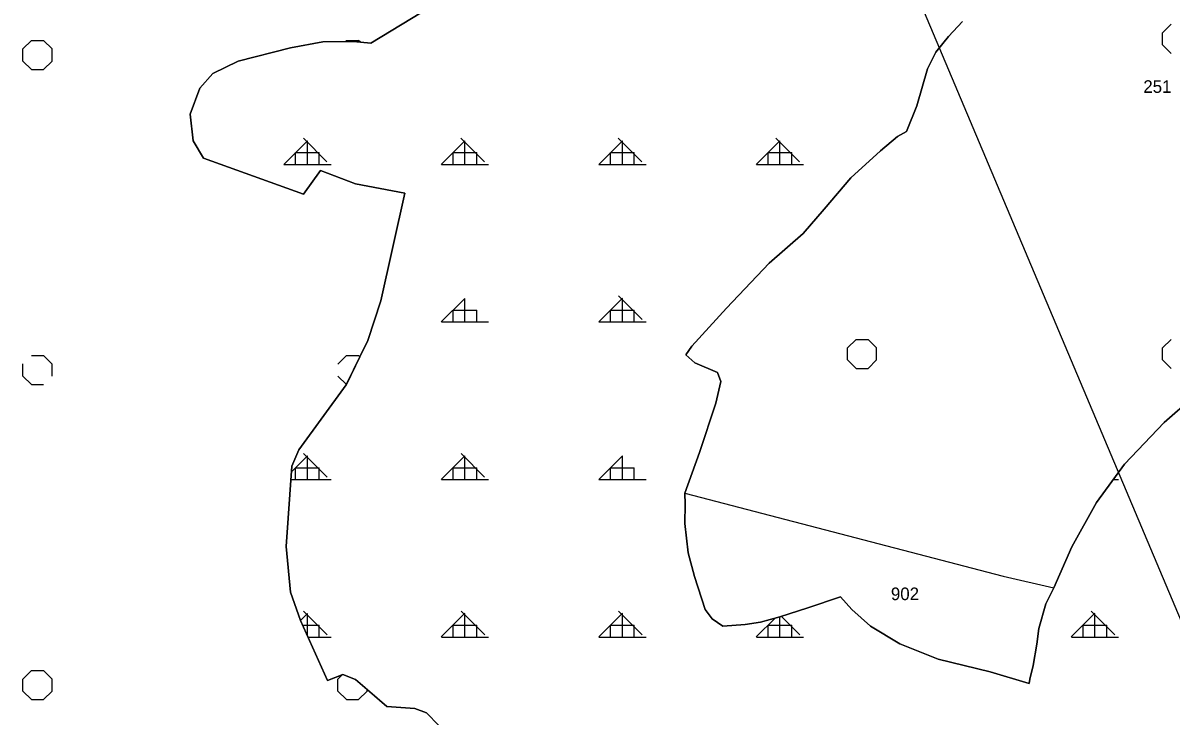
# Model space of a CAD drawing. Extents: x 410727 to 412947, y 4463506 to 4466382.
# Drawn here: x 411332 to 411696.5, y 4465172.3 to 4465392.3 of the extents above; entities that cross this region are included whole.
import ezdxf

# ---------------------------------------------------------------- set-up
doc = ezdxf.new("R2010")
doc.units = 0
for name, color, linetype in [('ADAKENARI', 7, 'Continuous'), ('KDS_PARSEL_NO', 7, 'Continuous'), ('KDS_PL', 7, 'Continuous'), ('LJ_ÇERÇEVE', 7, 'Continuous'), ('PL_AYA_ORMAN', 7, 'Continuous'), ('PL_KA_TARIM_DIGER', 7, 'Continuous'), ('TR_ORMAN', 7, 'Continuous'), ('TR_TARIMALANI', 7, 'Continuous')]:
    doc.layers.add(name, color=color, linetype=linetype)

msp = doc.modelspace()

# ---------------------------------------------------------------- linework, layer by layer
at = {"layer": 'ADAKENARI'}
for p, q in [((411442.41, 4465385.9), (411471.18, 4465403.51)), ((411630.3, 4465392.76), (411625.8, 4465388.07)), ((411416.96, 4465384.44), (411427.14, 4465386.32)), ((411427.14, 4465386.32), (411436.9, 4465386.42)), ((411436.9, 4465386.42), (411442.41, 4465385.9)), ((411436.9, 4465386.42), (411442.41, 4465385.9)), ((411625.8, 4465388.07), (411621.83, 4465383.02)), ((411400.33, 4465380.17), (411416.96, 4465384.44)), ((411621.83, 4465383.02), (411619.13, 4465377.78)), ((411392.23, 4465376.31), (411400.33, 4465380.17)), ((411619.13, 4465377.78), (411615.71, 4465366.05)), ((411388.18, 4465371.62), (411392.23, 4465376.31)), ((411385.06, 4465363.39), (411388.18, 4465371.62)), ((411386, 4465354.95), (411385.06, 4465363.39)), ((411615.71, 4465366.05), (411612.47, 4465357.93)), ((411609.59, 4465356.31), (411604.18, 4465351.79)), ((411612.47, 4465357.93), (411609.59, 4465356.31)), ((411389.32, 4465349.43), (411386, 4465354.95)), ((411421.01, 4465337.97), (411389.32, 4465349.43)), ((411604.18, 4465351.79), (411594.82, 4465343.13)), ((411426.41, 4465345.47), (411421.01, 4465337.97)), ((411437.53, 4465341.3), (411426.41, 4465345.47)), ((411453.21, 4465338.28), (411437.53, 4465341.3)), ((411594.82, 4465343.13), (411586.35, 4465333.21)), ((411445.63, 4465304.1), (411453.21, 4465338.28)), ((411586.35, 4465333.21), (411579.69, 4465325.45)), ((411579.69, 4465325.45), (411568.88, 4465316.06)), ((411568.88, 4465316.06), (411555.37, 4465301.8)), ((411441.47, 4465291.49), (411445.63, 4465304.1)), ((411555.37, 4465301.8), (411544.38, 4465289.71)), ((411434.62, 4465277.42), (411441.47, 4465291.49)), ((411544.38, 4465289.71), (411542.4, 4465287)), ((411542.4, 4465287), (411545.28, 4465284.48)), ((411545.28, 4465284.48), (411552.49, 4465281.41)), ((411552.49, 4465281.41), (411553.57, 4465278.52)), ((411419.55, 4465256.79), (411434.62, 4465277.42)), ((411553.57, 4465278.52), (411551.95, 4465271.67)), ((411694.29, 4465265.48), (411703.49, 4465273.54)), ((411551.95, 4465271.67), (411546.73, 4465255.96)), ((411681.65, 4465252.23), (411694.29, 4465265.48)), ((411417.37, 4465251.68), (411419.55, 4465256.79)), ((411546.73, 4465255.96), (411542.16, 4465243.04)), ((411415.6, 4465226.15), (411417.37, 4465251.68)), ((411672.74, 4465240.14), (411681.65, 4465252.23)), ((411542.16, 4465243.04), (411542.25, 4465239.55)), ((411542.25, 4465239.55), (411542.08, 4465233.43)), ((411664.98, 4465226.04), (411672.74, 4465240.14)), ((411542.08, 4465233.43), (411543.13, 4465224.15)), ((411416.96, 4465211.67), (411415.6, 4465226.15)), ((411659.3, 4465213.08), (411664.98, 4465226.04)), ((411543.13, 4465224.15), (411545.22, 4465216.63)), ((411545.22, 4465216.63), (411548.54, 4465206.13)), ((411420.07, 4465202.71), (411416.96, 4465211.67)), ((411581.2, 4465206.66), (411591.5, 4465210.16)), ((411591.5, 4465210.16), (411595.17, 4465206.13)), ((411656.74, 4465207.95), (411659.3, 4465213.08)), ((411572.29, 4465203.86), (411581.2, 4465206.66)), ((411654.52, 4465200.17), (411656.74, 4465207.95)), ((411428.69, 4465183.64), (411420.07, 4465202.71)), ((411548.54, 4465206.13), (411550.81, 4465203.16)), ((411550.81, 4465203.16), (411554.13, 4465200.88)), ((411566.18, 4465202.11), (411572.29, 4465203.86)), ((411595.17, 4465206.13), (411601.1, 4465200.88)), ((411554.13, 4465200.88), (411561.29, 4465201.41)), ((411561.29, 4465201.41), (411566.18, 4465202.11)), ((411601.1, 4465200.88), (411610.36, 4465195.28)), ((411653.82, 4465195.16), (411654.52, 4465200.17)), ((411610.36, 4465195.28), (411622.58, 4465190.38)), ((411652.71, 4465188.35), (411653.82, 4465195.16)), ((411622.58, 4465190.38), (411639, 4465186.36)), ((411651.6, 4465184.04), (411652.71, 4465188.35)), ((411433.58, 4465185.51), (411428.69, 4465183.64)), ((411437.53, 4465183.95), (411433.58, 4465185.51)), ((411639, 4465186.36), (411651.46, 4465182.65)), ((411447.5, 4465175.41), (411437.53, 4465183.95)), ((411651.46, 4465182.65), (411651.6, 4465184.04)), ((411456.43, 4465174.68), (411447.5, 4465175.41)), ((411460.07, 4465173.32), (411456.43, 4465174.68)), ((411464.02, 4465169.36), (411460.07, 4465173.32))]:
    msp.add_line(p, q, dxfattribs=at)
at = {"layer": 'KDS_PL'}
for p, q in [((411442.41, 4465385.9), (411471.18, 4465403.51)), ((411625.8, 4465388.07), (411630.3, 4465392.76)), ((411416.96, 4465384.44), (411427.14, 4465386.32)), ((411427.14, 4465386.32), (411436.9, 4465386.42)), ((411436.9, 4465386.42), (411442.41, 4465385.9)), ((411621.83, 4465383.02), (411625.8, 4465388.07)), ((411400.33, 4465380.17), (411416.96, 4465384.44)), ((411619.13, 4465377.78), (411621.83, 4465383.02)), ((411392.23, 4465376.31), (411400.33, 4465380.17)), ((411615.71, 4465366.05), (411619.13, 4465377.78)), ((411388.18, 4465371.62), (411392.23, 4465376.31)), ((411385.06, 4465363.39), (411388.18, 4465371.62)), ((411386, 4465354.95), (411385.06, 4465363.39)), ((411612.47, 4465357.93), (411615.71, 4465366.05)), ((411604.18, 4465351.79), (411609.59, 4465356.31)), ((411609.59, 4465356.31), (411612.47, 4465357.93)), ((411389.32, 4465349.43), (411386, 4465354.95)), ((411421.01, 4465337.97), (411389.32, 4465349.43)), ((411594.82, 4465343.13), (411604.18, 4465351.79)), ((411426.41, 4465345.47), (411421.01, 4465337.97)), ((411437.53, 4465341.3), (411426.41, 4465345.47)), ((411453.21, 4465338.28), (411437.53, 4465341.3)), ((411586.35, 4465333.21), (411594.82, 4465343.13)), ((411445.63, 4465304.1), (411453.21, 4465338.28)), ((411579.69, 4465325.45), (411586.35, 4465333.21)), ((411568.88, 4465316.06), (411579.69, 4465325.45)), ((411555.37, 4465301.8), (411568.88, 4465316.06)), ((411441.47, 4465291.49), (411445.63, 4465304.1)), ((411544.38, 4465289.71), (411555.37, 4465301.8)), ((411434.62, 4465277.42), (411441.47, 4465291.49)), ((411542.4, 4465287), (411544.38, 4465289.71)), ((411545.28, 4465284.48), (411542.4, 4465287)), ((411552.49, 4465281.41), (411545.28, 4465284.48)), ((411553.57, 4465278.52), (411552.49, 4465281.41)), ((411419.55, 4465256.79), (411434.62, 4465277.42)), ((411551.95, 4465271.67), (411553.57, 4465278.52)), ((411694.29, 4465265.48), (411703.49, 4465273.54)), ((411546.73, 4465255.96), (411551.95, 4465271.67)), ((411681.65, 4465252.23), (411694.29, 4465265.48)), ((411417.37, 4465251.68), (411419.55, 4465256.79)), ((411542.16, 4465243.04), (411546.73, 4465255.96)), ((411415.6, 4465226.15), (411417.37, 4465251.68)), ((411672.74, 4465240.14), (411681.65, 4465252.23)), ((411542.16, 4465243.04), (411643.13, 4465216.75)), ((411542.25, 4465239.55), (411542.16, 4465243.04)), ((411542.08, 4465233.43), (411542.25, 4465239.55)), ((411664.98, 4465226.04), (411672.74, 4465240.14)), ((411543.13, 4465224.15), (411542.08, 4465233.43)), ((411416.96, 4465211.67), (411415.6, 4465226.15)), ((411659.3, 4465213.08), (411664.98, 4465226.04)), ((411545.22, 4465216.63), (411543.13, 4465224.15)), ((411548.54, 4465206.13), (411545.22, 4465216.63)), ((411643.13, 4465216.75), (411659.3, 4465213.08)), ((411420.07, 4465202.71), (411416.96, 4465211.67)), ((411591.5, 4465210.16), (411581.2, 4465206.66)), ((411595.17, 4465206.13), (411591.5, 4465210.16)), ((411659.3, 4465213.08), (411656.74, 4465207.95)), ((411581.2, 4465206.66), (411572.29, 4465203.86)), ((411656.74, 4465207.95), (411654.52, 4465200.17)), ((411428.69, 4465183.64), (411420.07, 4465202.71)), ((411550.81, 4465203.16), (411548.54, 4465206.13)), ((411554.13, 4465200.88), (411550.81, 4465203.16)), ((411572.29, 4465203.86), (411566.18, 4465202.11)), ((411601.1, 4465200.88), (411595.17, 4465206.13)), ((411561.29, 4465201.41), (411554.13, 4465200.88)), ((411566.18, 4465202.11), (411561.29, 4465201.41)), ((411610.36, 4465195.28), (411601.1, 4465200.88)), ((411654.52, 4465200.17), (411653.82, 4465195.16)), ((411622.58, 4465190.38), (411610.36, 4465195.28)), ((411653.82, 4465195.16), (411652.71, 4465188.35)), ((411639, 4465186.36), (411622.58, 4465190.38)), ((411652.71, 4465188.35), (411651.6, 4465184.04)), ((411433.58, 4465185.51), (411428.69, 4465183.64)), ((411437.53, 4465183.95), (411433.58, 4465185.51)), ((411651.46, 4465182.65), (411639, 4465186.36)), ((411447.5, 4465175.41), (411437.53, 4465183.95)), ((411651.6, 4465184.04), (411651.46, 4465182.65)), ((411456.43, 4465174.68), (411447.5, 4465175.41)), ((411460.07, 4465173.32), (411456.43, 4465174.68)), ((411464.02, 4465169.36), (411460.07, 4465173.32))]:
    msp.add_line(p, q, dxfattribs=at)
at = {"layer": 'LJ_ÇERÇEVE'}
msp.add_line((412177.76, 4464068.35), (411528.62, 4465608.26), dxfattribs=at)
at = {"layer": 'PL_AYA_ORMAN'}
for points in [[(411471.18, 4465403.51), (411442.41, 4465385.9), (411439.11, 4465386.21), (411436.9, 4465386.42), (411434.31, 4465386.39), (411427.14, 4465386.32), (411416.96, 4465384.44), (411400.33, 4465380.17), (411392.23, 4465376.31), (411388.18, 4465371.62), (411385.06, 4465363.39), (411386, 4465354.95), (411389.32, 4465349.43), (411421.01, 4465337.97), (411426.41, 4465345.47), (411437.53, 4465341.3), (411453.21, 4465338.28), (411445.63, 4465304.1), (411441.47, 4465291.49), (411438.97, 4465286.35), (411434.68, 4465277.56), (411434.62, 4465277.42), (411419.55, 4465256.79), (411417.37, 4465251.68), (411415.6, 4465226.15), (411416.96, 4465211.67), (411420.07, 4465202.71), (411428.69, 4465183.64), (411433.34, 4465185.42), (411433.58, 4465185.51), (411437.53, 4465183.95), (411441.25, 4465180.76), (411447.5, 4465175.41), (411456.43, 4465174.68), (411460.07, 4465173.32), (411464.02, 4465169.36)], [(411703.49, 4465273.54), (411694.29, 4465265.48), (411681.65, 4465252.23), (411672.74, 4465240.14), (411664.98, 4465226.04), (411659.3, 4465213.08), (411656.74, 4465207.95), (411654.52, 4465200.17), (411653.82, 4465195.16), (411652.71, 4465188.35), (411651.6, 4465184.04), (411651.46, 4465182.65), (411639, 4465186.36), (411622.58, 4465190.38), (411610.36, 4465195.28), (411601.1, 4465200.88), (411595.17, 4465206.13), (411591.5, 4465210.16), (411581.2, 4465206.66), (411572.29, 4465203.86), (411566.18, 4465202.11), (411561.29, 4465201.41), (411554.13, 4465200.88), (411550.81, 4465203.16), (411548.54, 4465206.13), (411545.22, 4465216.63), (411543.13, 4465224.15), (411542.08, 4465233.43), (411542.25, 4465239.55), (411542.16, 4465243.04), (411546.73, 4465255.96), (411551.95, 4465271.67), (411553.57, 4465278.52), (411552.49, 4465281.41), (411545.28, 4465284.48), (411542.4, 4465287), (411544.38, 4465289.71), (411555.37, 4465301.8), (411568.88, 4465316.06), (411579.69, 4465325.45), (411586.35, 4465333.21), (411594.82, 4465343.13), (411604.18, 4465351.79), (411609.59, 4465356.31), (411612.47, 4465357.93), (411615.71, 4465366.05), (411619.13, 4465377.78), (411621.83, 4465383.02), (411625.8, 4465388.07), (411630.3, 4465392.76)]]:
    msp.add_lwpolyline(points, dxfattribs=at)
at = {"layer": 'PL_KA_TARIM_DIGER'}
for points in [[(411464.02, 4465169.36), (411460.07, 4465173.32), (411456.43, 4465174.68), (411447.5, 4465175.41), (411437.53, 4465183.95), (411433.58, 4465185.51), (411428.69, 4465183.64), (411420.07, 4465202.71), (411416.96, 4465211.67), (411415.6, 4465226.15), (411417.37, 4465251.68), (411419.55, 4465256.79), (411434.62, 4465277.42), (411441.47, 4465291.49), (411445.63, 4465304.1), (411453.21, 4465338.28), (411437.53, 4465341.3), (411426.41, 4465345.47), (411421.01, 4465337.97), (411389.32, 4465349.43), (411386, 4465354.95), (411385.06, 4465363.39), (411388.18, 4465371.62), (411392.23, 4465376.31), (411400.33, 4465380.17), (411416.96, 4465384.44), (411427.14, 4465386.32), (411436.9, 4465386.42), (411442.41, 4465385.9), (411471.18, 4465403.51)], [(411630.3, 4465392.76), (411625.8, 4465388.07), (411621.83, 4465383.02), (411619.13, 4465377.78), (411615.71, 4465366.05), (411612.47, 4465357.93), (411609.59, 4465356.31), (411604.18, 4465351.79), (411594.82, 4465343.13), (411586.35, 4465333.21), (411579.69, 4465325.45), (411568.88, 4465316.06), (411555.37, 4465301.8), (411544.38, 4465289.71), (411542.4, 4465287), (411545.28, 4465284.48), (411552.49, 4465281.41), (411553.57, 4465278.52), (411551.95, 4465271.67), (411546.73, 4465255.96), (411542.16, 4465243.04), (411542.25, 4465239.55), (411542.08, 4465233.43), (411543.13, 4465224.15), (411545.22, 4465216.63), (411548.54, 4465206.13), (411550.81, 4465203.16), (411554.13, 4465200.88), (411561.29, 4465201.41), (411566.18, 4465202.11), (411572.29, 4465203.86), (411581.2, 4465206.66), (411591.5, 4465210.16), (411595.17, 4465206.13), (411601.1, 4465200.88), (411610.36, 4465195.28), (411622.58, 4465190.38), (411639, 4465186.36), (411651.46, 4465182.65), (411651.6, 4465184.04), (411652.71, 4465188.35), (411653.82, 4465195.16), (411654.52, 4465200.17), (411656.74, 4465207.95), (411659.3, 4465213.08), (411664.98, 4465226.04), (411672.74, 4465240.14), (411681.65, 4465252.23), (411694.29, 4465265.48), (411703.49, 4465273.54)]]:
    msp.add_lwpolyline(points, dxfattribs=at)
at = {"layer": 'TR_ORMAN'}
for p, q in [((411428.5, 4465348.21), (411421, 4465355.71)), ((411428.5, 4465348.21), (411421, 4465355.71)), ((411478.49, 4465348.21), (411470.99, 4465355.71)), ((411528.48, 4465348.21), (411520.99, 4465355.71)), ((411578.48, 4465348.21), (411570.98, 4465355.71)), ((411414.8, 4465347.41), (411422.3, 4465354.91)), ((411414.8, 4465347.41), (411422.3, 4465354.91)), ((411422.31, 4465347.41), (411422.31, 4465354.91)), ((411422.31, 4465347.41), (411422.31, 4465354.91)), ((411464.8, 4465347.41), (411472.3, 4465354.91)), ((411464.8, 4465347.41), (411472.3, 4465354.91)), ((411472.31, 4465347.41), (411472.31, 4465354.91)), ((411472.31, 4465347.41), (411472.31, 4465354.91)), ((411514.8, 4465347.42), (411522.29, 4465354.92)), ((411522.31, 4465347.41), (411522.31, 4465354.91)), ((411564.8, 4465347.43), (411572.29, 4465354.93)), ((411572.31, 4465347.41), (411572.31, 4465354.91)), ((411418.56, 4465347.41), (411418.56, 4465351.16)), ((411418.56, 4465347.41), (411418.56, 4465351.16)), ((411418.56, 4465351.16), (411426.06, 4465351.16)), ((411426.06, 4465347.41), (411426.06, 4465351.16)), ((411426.06, 4465347.41), (411426.06, 4465351.16)), ((411468.56, 4465347.41), (411468.56, 4465351.16)), ((411468.56, 4465347.41), (411468.56, 4465351.16)), ((411468.56, 4465351.16), (411476.06, 4465351.16)), ((411476.06, 4465347.41), (411476.06, 4465351.16)), ((411476.06, 4465347.41), (411476.06, 4465351.16)), ((411518.56, 4465347.41), (411518.56, 4465351.16)), ((411518.56, 4465351.16), (411526.06, 4465351.16)), ((411526.06, 4465347.41), (411526.06, 4465351.16)), ((411568.56, 4465347.41), (411568.56, 4465351.16)), ((411568.56, 4465351.16), (411576.06, 4465351.16)), ((411576.06, 4465347.41), (411576.06, 4465351.16)), ((411414.81, 4465347.41), (411429.81, 4465347.41)), ((411464.81, 4465347.41), (411479.81, 4465347.41)), ((411514.81, 4465347.41), (411529.81, 4465347.41)), ((411564.81, 4465347.41), (411579.81, 4465347.41)), ((411464.8, 4465297.42), (411472.3, 4465304.92)), ((411472.31, 4465297.41), (411472.31, 4465304.91)), ((411472.31, 4465297.41), (411472.31, 4465304.91)), ((411514.8, 4465297.43), (411522.29, 4465304.93)), ((411528.52, 4465298.18), (411521.02, 4465305.68)), ((411522.31, 4465297.41), (411522.31, 4465304.91)), ((411468.56, 4465297.41), (411468.56, 4465301.16)), ((411468.56, 4465297.41), (411468.56, 4465301.16)), ((411468.56, 4465301.16), (411476.06, 4465301.16)), ((411476.06, 4465297.41), (411476.06, 4465301.16)), ((411476.06, 4465297.41), (411476.06, 4465301.16)), ((411518.56, 4465297.41), (411518.56, 4465301.16)), ((411518.56, 4465301.16), (411526.06, 4465301.16)), ((411526.06, 4465297.41), (411526.06, 4465301.16)), ((411464.81, 4465297.41), (411479.81, 4465297.41)), ((411514.81, 4465297.41), (411529.81, 4465297.41)), ((411417.25, 4465249.87), (411422.3, 4465254.92)), ((411428.56, 4465248.16), (411421.06, 4465255.66)), ((411422.31, 4465247.41), (411422.31, 4465254.91)), ((411464.8, 4465247.43), (411472.3, 4465254.93)), ((411478.56, 4465248.16), (411471.06, 4465255.66)), ((411472.31, 4465247.41), (411472.31, 4465254.91)), ((411472.31, 4465247.41), (411472.31, 4465254.91)), ((411514.8, 4465247.44), (411522.29, 4465254.93)), ((411522.31, 4465247.41), (411522.31, 4465254.91)), ((411418.56, 4465251.16), (411426.06, 4465251.16)), ((411418.56, 4465247.41), (411418.56, 4465251.16)), ((411426.06, 4465247.41), (411426.06, 4465251.16)), ((411468.56, 4465251.16), (411476.06, 4465251.16)), ((411468.56, 4465247.41), (411468.56, 4465251.16)), ((411468.56, 4465247.41), (411468.56, 4465251.16)), ((411476.06, 4465247.41), (411476.06, 4465251.16)), ((411476.06, 4465247.41), (411476.06, 4465251.16)), ((411518.56, 4465251.16), (411526.06, 4465251.16)), ((411518.56, 4465247.41), (411518.56, 4465251.16)), ((411526.06, 4465247.41), (411526.06, 4465251.16)), ((411417.08, 4465247.41), (411429.81, 4465247.41)), ((411464.81, 4465247.41), (411479.81, 4465247.41)), ((411514.81, 4465247.41), (411529.81, 4465247.41)), ((411678.1, 4465247.41), (411679.81, 4465247.41)), ((411678.1, 4465247.41), (411679.81, 4465247.41)), ((411420.07, 4465202.71), (411422.3, 4465204.93)), ((411428.59, 4465198.14), (411421.1, 4465205.64)), ((411422.31, 4465197.75), (411422.31, 4465204.91)), ((411464.8, 4465197.44), (411472.3, 4465204.94)), ((411478.59, 4465198.14), (411471.09, 4465205.64)), ((411472.31, 4465197.41), (411472.31, 4465204.91)), ((411472.31, 4465197.41), (411472.31, 4465204.91)), ((411514.8, 4465197.44), (411522.29, 4465204.94)), ((411528.58, 4465198.14), (411521.08, 4465205.64)), ((411522.31, 4465197.41), (411522.31, 4465204.91)), ((411564.8, 4465197.45), (411570.77, 4465203.42)), ((411572.31, 4465197.41), (411572.31, 4465203.86)), ((411578.57, 4465198.14), (411572.72, 4465203.99)), ((411664.79, 4465197.46), (411672.29, 4465204.96)), ((411678.56, 4465198.14), (411671.06, 4465205.64)), ((411672.31, 4465197.41), (411672.31, 4465204.91)), ((411420.77, 4465201.16), (411426.06, 4465201.16)), ((411426.06, 4465197.41), (411426.06, 4465201.16)), ((411468.56, 4465197.41), (411468.56, 4465201.16)), ((411468.56, 4465197.41), (411468.56, 4465201.16)), ((411468.56, 4465201.16), (411476.06, 4465201.16)), ((411476.06, 4465197.41), (411476.06, 4465201.16)), ((411476.06, 4465197.41), (411476.06, 4465201.16)), ((411518.56, 4465197.41), (411518.56, 4465201.16)), ((411518.56, 4465201.16), (411526.06, 4465201.16)), ((411526.06, 4465197.41), (411526.06, 4465201.16)), ((411568.56, 4465197.41), (411568.56, 4465201.16)), ((411568.56, 4465201.16), (411576.06, 4465201.16)), ((411576.06, 4465197.41), (411576.06, 4465201.16)), ((411668.56, 4465197.41), (411668.56, 4465201.16)), ((411668.56, 4465201.16), (411676.06, 4465201.16)), ((411668.56, 4465201.16), (411676.06, 4465201.16)), ((411676.06, 4465197.41), (411676.06, 4465201.16)), ((411422.47, 4465197.41), (411429.81, 4465197.41)), ((411464.81, 4465197.41), (411479.81, 4465197.41)), ((411514.81, 4465197.41), (411529.81, 4465197.41)), ((411564.81, 4465197.41), (411579.81, 4465197.41)), ((411664.81, 4465197.41), (411679.81, 4465197.41)), ((411664.81, 4465197.41), (411679.81, 4465197.41))]:
    msp.add_line(p, q, dxfattribs=at)
at = {"layer": 'TR_TARIMALANI'}
for p, q in [((411693.74, 4465389.19), (411696.45, 4465391.9)), ((411693.74, 4465389.19), (411696.45, 4465391.9)), ((411693.75, 4465385.36), (411693.75, 4465389.19)), ((411693.75, 4465385.36), (411693.75, 4465389.19)), ((411332, 4465384.07), (411334.7, 4465386.78)), ((411332, 4465384.07), (411334.7, 4465386.78)), ((411334.71, 4465386.79), (411338.54, 4465386.79)), ((411334.71, 4465386.79), (411338.54, 4465386.79)), ((411341.25, 4465384.07), (411338.54, 4465386.78)), ((411341.25, 4465384.07), (411338.54, 4465386.78)), ((411434.31, 4465386.39), (411434.7, 4465386.78)), ((411434.31, 4465386.39), (411434.7, 4465386.78)), ((411434.71, 4465386.79), (411438.54, 4465386.79)), ((411439.11, 4465386.21), (411438.54, 4465386.78)), ((411696.45, 4465382.65), (411693.74, 4465385.36)), ((411696.45, 4465382.65), (411693.74, 4465385.36)), ((411332, 4465380.25), (411332, 4465384.08)), ((411332, 4465380.25), (411332, 4465384.08)), ((411341.25, 4465380.25), (411341.25, 4465384.08)), ((411341.25, 4465380.25), (411341.25, 4465384.08)), ((411334.71, 4465377.53), (411332, 4465380.24)), ((411334.71, 4465377.53), (411332, 4465380.24)), ((411334.71, 4465377.54), (411338.54, 4465377.54)), ((411334.71, 4465377.54), (411338.54, 4465377.54)), ((411338.54, 4465377.53), (411341.24, 4465380.24)), ((411338.54, 4465377.53), (411341.24, 4465380.24)), ((411593.74, 4465289.19), (411596.45, 4465291.9)), ((411593.74, 4465289.19), (411596.45, 4465291.9)), ((411596.46, 4465291.9), (411600.29, 4465291.9)), ((411596.46, 4465291.9), (411600.29, 4465291.9)), ((411602.99, 4465289.19), (411600.28, 4465291.9)), ((411602.99, 4465289.19), (411600.28, 4465291.9)), ((411693.74, 4465289.19), (411696.45, 4465291.9)), ((411693.74, 4465289.19), (411696.45, 4465291.9)), ((411334.71, 4465286.79), (411338.54, 4465286.79)), ((411334.71, 4465286.79), (411338.54, 4465286.79)), ((411334.71, 4465286.79), (411338.54, 4465286.79)), ((411334.71, 4465286.79), (411338.54, 4465286.79)), ((411341.25, 4465284.07), (411338.54, 4465286.78)), ((411341.25, 4465284.07), (411338.54, 4465286.78)), ((411431.99, 4465284.07), (411434.7, 4465286.78)), ((411434.71, 4465286.79), (411438.54, 4465286.79)), ((411434.71, 4465286.79), (411438.54, 4465286.79)), ((411438.97, 4465286.35), (411438.54, 4465286.78)), ((411593.75, 4465285.36), (411593.75, 4465289.19)), ((411593.75, 4465285.36), (411593.75, 4465289.19)), ((411603, 4465285.36), (411603, 4465289.19)), ((411603, 4465285.36), (411603, 4465289.19)), ((411693.75, 4465285.36), (411693.75, 4465289.19)), ((411693.75, 4465285.36), (411693.75, 4465289.19)), ((411332, 4465280.25), (411332, 4465284.08)), ((411332, 4465280.25), (411332, 4465284.08)), ((411341.25, 4465280.25), (411341.25, 4465284.08)), ((411341.25, 4465280.25), (411341.25, 4465284.08)), ((411596.45, 4465282.65), (411593.74, 4465285.36)), ((411596.45, 4465282.65), (411593.74, 4465285.36)), ((411600.28, 4465282.65), (411602.99, 4465285.36)), ((411600.28, 4465282.65), (411602.99, 4465285.36)), ((411696.45, 4465282.65), (411693.74, 4465285.36)), ((411696.45, 4465282.65), (411693.74, 4465285.36)), ((411334.71, 4465277.53), (411332, 4465280.24)), ((411334.71, 4465277.53), (411332, 4465280.24)), ((411434.68, 4465277.56), (411432, 4465280.24)), ((411596.46, 4465282.65), (411600.29, 4465282.65)), ((411596.46, 4465282.65), (411600.29, 4465282.65)), ((411334.71, 4465277.54), (411338.54, 4465277.54)), ((411334.71, 4465277.54), (411338.54, 4465277.54)), ((411334.71, 4465277.54), (411338.54, 4465277.54)), ((411334.71, 4465277.54), (411338.54, 4465277.54)), ((411332, 4465184.08), (411334.7, 4465186.78)), ((411332, 4465184.08), (411334.7, 4465186.78)), ((411334.71, 4465186.79), (411338.54, 4465186.79)), ((411334.71, 4465186.79), (411338.54, 4465186.79)), ((411341.25, 4465184.08), (411338.54, 4465186.78)), ((411341.25, 4465184.08), (411338.54, 4465186.78)), ((411431.99, 4465184.08), (411433.34, 4465185.42)), ((411332, 4465180.25), (411332, 4465184.08)), ((411332, 4465180.25), (411332, 4465184.08)), ((411341.25, 4465180.25), (411341.25, 4465184.08)), ((411341.25, 4465180.25), (411341.25, 4465184.08)), ((411432, 4465180.25), (411432, 4465184.08)), ((411441.25, 4465180.25), (411441.25, 4465180.76)), ((411334.71, 4465177.54), (411332, 4465180.24)), ((411334.71, 4465177.54), (411332, 4465180.24)), ((411334.71, 4465177.54), (411338.54, 4465177.54)), ((411334.71, 4465177.54), (411338.54, 4465177.54)), ((411338.54, 4465177.54), (411341.24, 4465180.24)), ((411338.54, 4465177.54), (411341.24, 4465180.24)), ((411434.7, 4465177.54), (411432, 4465180.24)), ((411434.71, 4465177.54), (411438.54, 4465177.54)), ((411438.53, 4465177.54), (411441.24, 4465180.24))]:
    msp.add_line(p, q, dxfattribs=at)

# ---------------------------------------------------------------- texts
at = {"layer": 'KDS_PARSEL_NO'}
for s, p in [('251', (411687.66, 4465370.14)), ('902', (411607.53, 4465209.12))]:
    msp.add_text(s, height=4, dxfattribs=at).set_placement(p)

doc.saveas('drawing.dxf')
